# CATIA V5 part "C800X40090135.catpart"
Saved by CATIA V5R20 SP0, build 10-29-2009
Part number: C800X40090135
Source: Unknown
Property "A": "90"
Property "ARTICLENO": "C800X40090135"
Property "B": "45"
Property "BOMINFO": "C800X40090135"
Property "C": "124"
Property "CA": "C800X40090135"
Property "D1": "170"
Property "DES": "ROTATING EYEBOLT WITH RING Ton 40,0 M90x135"
Property "E": "165"
Property "H": "333"
Property "L": "135"
Property "LINA": "C800X40090135"
Property "NB": "C800X40090135"
Property "NBSYN": "$CODE."
Property "NN": "C800X"
Property "NT": "Rotating eyebolt with ring"
Property "SIZE": "M90"
Property "SUPPLIER": "CF"
Property "SW": "134"
Property "WEIGHT": "29000"
Property "WLL": "40.00"
Bounding box of the stored display mesh (mm): x -90 to 90, y -135 to 378, z -85 to 85
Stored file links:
  C:\Users\Utente\Desktop\3D files 800X\C800X40090135.catpart

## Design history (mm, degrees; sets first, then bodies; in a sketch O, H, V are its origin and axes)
Body1 "Geometry.1" (main body)
  Solid1 "C800X40090135.catpart": solid without history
